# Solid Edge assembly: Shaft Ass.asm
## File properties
Title: Shaft Assembly
Last saved by: Dan
Revision: 131
Project Name: Piston Pump P52
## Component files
Pump Shaft.par
Thrust & Roller Bearing 44,85,22.asm
Thrust Bearing 44,85,12.asm
n024680c 009ODF5R.par
Snap Ring 42 Shaft.par
Snap Ring 35 Shaft.par
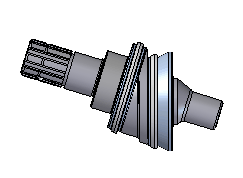
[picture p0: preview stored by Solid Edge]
